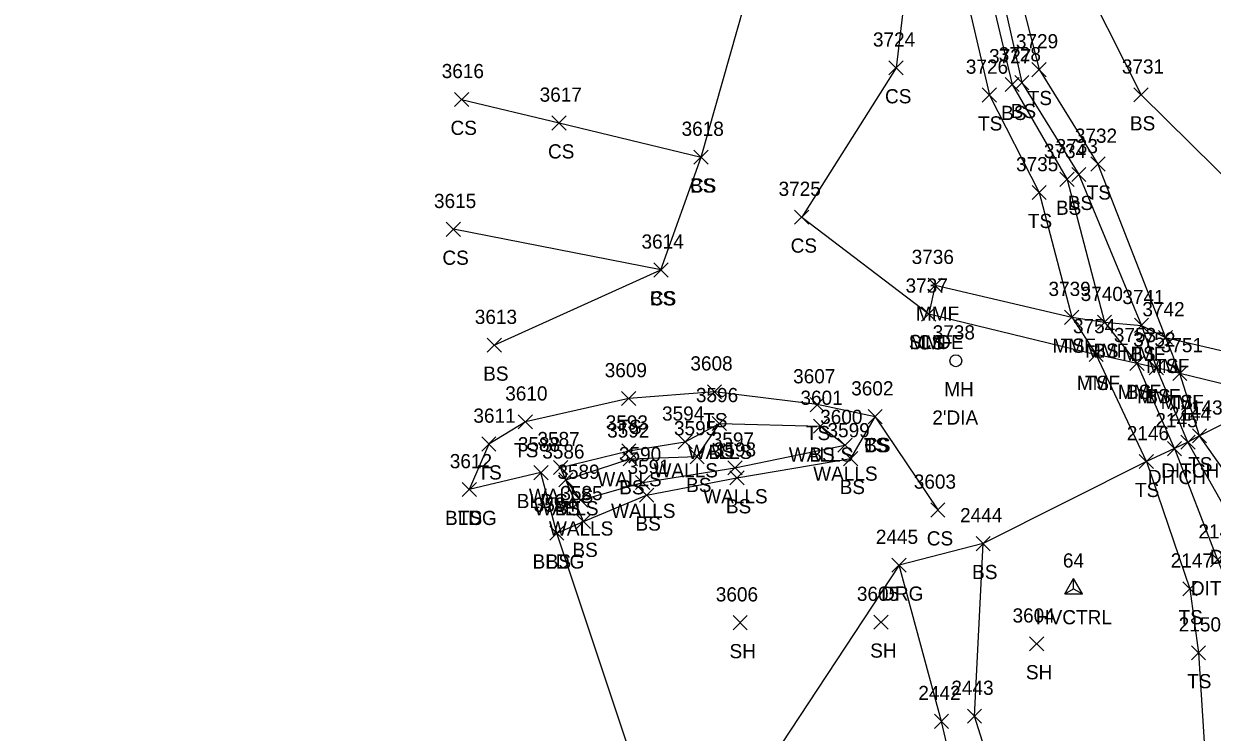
# Model space of a CAD drawing. Extents: x 49137 to 50946, y 9590 to 10709.
# Drawn here: x 49797.9 to 49965.3, y 10186.5 to 10286.3 of the extents above; entities that cross this region are included whole.
import ezdxf

# ---------------------------------------------------------------- set-up
doc = ezdxf.new("R2010")
doc.units = 0
for name, color, linetype in [('C_A', 7, 'Continuous'), ('C_I', 7, 'Continuous'), ('CPSM', 7, 'Continuous'), ('D_A', 7, 'Continuous'), ('D_I', 7, 'Continuous'), ('D_TIC', 7, 'Continuous'), ('DD', 7, 'Continuous'), ('L_A', 7, 'Continuous'), ('L_C', 7, 'Continuous'), ('L_I', 7, 'Continuous'), ('L_TIC', 7, 'Continuous'), ('LBC', 7, 'Continuous'), ('LDEFAULT', 7, 'Continuous'), ('LELB', 7, 'Continuous'), ('LSOGP', 7, 'Continuous'), ('LWS', 7, 'Continuous'), ('R_A', 7, 'Continuous'), ('R_I', 7, 'Continuous'), ('R_TIC', 7, 'Continuous'), ('RDG', 7, 'Continuous'), ('U_A', 7, 'Continuous'), ('U_C', 7, 'Continuous'), ('U_I', 7, 'Continuous'), ('UDEFAULT', 7, 'Continuous'), ('UUMH', 7, 'Continuous')]:
    doc.layers.add(name, color=color, linetype=linetype)

msp = doc.modelspace()

# ---------------------------------------------------------------- linework, layer by layer
at = {"layer": 'CPSM'}
for p, q in [((49944.49, 10206.01), (49945.74, 10208.17)), ((49946.99, 10206.01), (49945.74, 10208.17)), ((49945.74, 10206.73), (49945.74, 10208.17)), ((49944.49, 10206.01), (49945.74, 10206.73)), ((49944.49, 10206.01), (49946.99, 10206.01)), ((49945.74, 10206.73), (49945.74, 10206.73)), ((49945.74, 10206.73), (49946.99, 10206.01))]:
    msp.add_line(p, q, dxfattribs=at)
at = {"layer": 'D_TIC'}
for points in [[(49960.84, 10226.4), (49962.84, 10228.4)], [(49962.84, 10226.4), (49960.84, 10228.4)], [(49958.95, 10225.49), (49960.95, 10227.49)], [(49960.95, 10225.49), (49958.95, 10227.49)], [(49965.02, 10209.83), (49967.02, 10211.83)], [(49967.02, 10209.83), (49965.02, 10211.83)]]:
    msp.add_lwpolyline(points, dxfattribs=at)
at = {"layer": 'DD'}
for points in [[(49959.95, 10226.49), (49954.67, 10238.49)], [(49961.84, 10227.4), (49957.39, 10237.87)], [(49959.95, 10226.49), (49966.02, 10210.83), (49969.21, 10203.1), (49971.52, 10178.36), (49977.72, 10168.94)], [(49984.26, 10173.72), (49979.3, 10173.63), (49975.22, 10179.6), (49971.2, 10205.48), (49968.69, 10215.24), (49961.84, 10227.4)]]:
    msp.add_lwpolyline(points, dxfattribs=at)
at = {"layer": 'L_TIC'}
for points in [[(49919.74, 10279.13), (49921.74, 10281.13)], [(49921.74, 10279.13), (49919.74, 10281.13)], [(49939.87, 10278.88), (49941.87, 10280.88)], [(49941.87, 10278.88), (49939.87, 10280.88)], [(49936.09, 10276.78), (49938.09, 10278.78)], [(49938.09, 10276.78), (49936.09, 10278.78)], [(49937.45, 10277.05), (49939.45, 10279.05)], [(49939.45, 10277.05), (49937.45, 10279.05)], [(49858.55, 10274.68), (49860.55, 10276.68)], [(49860.55, 10274.68), (49858.55, 10276.68)], [(49932.87, 10275.3), (49934.87, 10277.3)], [(49934.87, 10275.3), (49932.87, 10277.3)], [(49954.23, 10275.32), (49956.23, 10277.32)], [(49956.23, 10275.32), (49954.23, 10277.32)], [(49872.28, 10271.36), (49874.28, 10273.36)], [(49874.28, 10271.36), (49872.28, 10273.36)], [(49892.27, 10266.55), (49894.27, 10268.55)], [(49894.27, 10266.55), (49892.27, 10268.55)], [(49892.27, 10266.55), (49894.27, 10268.55)], [(49894.27, 10266.55), (49892.27, 10268.55)], [(49948.17, 10265.57), (49950.17, 10267.57)], [(49950.17, 10265.57), (49948.17, 10267.57)], [(49943.81, 10263.42), (49945.81, 10265.42)], [(49945.81, 10263.42), (49943.81, 10265.42)], [(49945.47, 10264.1), (49947.47, 10266.1)], [(49947.47, 10264.1), (49945.47, 10266.1)], [(49939.89, 10261.56), (49941.89, 10263.56)], [(49941.89, 10261.56), (49939.89, 10263.56)], [(49906.45, 10258.09), (49908.45, 10260.09)], [(49908.45, 10258.09), (49906.45, 10260.09)], [(49857.4, 10256.38), (49859.4, 10258.38)], [(49859.4, 10256.38), (49857.4, 10258.38)], [(49886.63, 10250.66), (49888.63, 10252.66)], [(49888.63, 10250.66), (49886.63, 10252.66)], [(49886.63, 10250.66), (49888.63, 10252.66)], [(49888.63, 10250.66), (49886.63, 10252.66)], [(49925.25, 10248.5), (49927.25, 10250.5)], [(49927.25, 10248.5), (49925.25, 10250.5)], [(49925.25, 10248.5), (49927.25, 10250.5)], [(49927.25, 10248.5), (49925.25, 10250.5)], [(49924.33, 10244.46), (49926.33, 10246.46)], [(49926.33, 10244.46), (49924.33, 10246.46)], [(49924.33, 10244.46), (49926.33, 10246.46)], [(49926.33, 10244.46), (49924.33, 10246.46)], [(49944.47, 10243.99), (49946.47, 10245.99)], [(49946.47, 10243.99), (49944.47, 10245.99)], [(49944.47, 10243.99), (49946.47, 10245.99)], [(49946.47, 10243.99), (49944.47, 10245.99)], [(49949.08, 10243.28), (49951.08, 10245.28)], [(49951.08, 10243.28), (49949.08, 10245.28)], [(49949.08, 10243.28), (49951.08, 10245.28)], [(49951.08, 10243.28), (49949.08, 10245.28)], [(49954.29, 10242.85), (49956.29, 10244.85)], [(49956.29, 10242.85), (49954.29, 10244.85)], [(49954.29, 10242.85), (49956.29, 10244.85)], [(49956.29, 10242.85), (49954.29, 10244.85)], [(49957.68, 10241.13), (49959.68, 10243.13)], [(49959.68, 10241.13), (49957.68, 10243.13)], [(49957.68, 10241.13), (49959.68, 10243.13)], [(49959.68, 10241.13), (49957.68, 10243.13)], [(49863.15, 10240.05), (49865.15, 10242.05)], [(49865.15, 10240.05), (49863.15, 10242.05)], [(49947.91, 10238.74), (49949.91, 10240.74)], [(49949.91, 10238.74), (49947.91, 10240.74)], [(49947.91, 10238.74), (49949.91, 10240.74)], [(49949.91, 10238.74), (49947.91, 10240.74)], [(49947.91, 10238.74), (49949.91, 10240.74)], [(49949.91, 10238.74), (49947.91, 10240.74)], [(49953.67, 10237.49), (49955.67, 10239.49)], [(49955.67, 10237.49), (49953.67, 10239.49)], [(49953.67, 10237.49), (49955.67, 10239.49)], [(49955.67, 10237.49), (49953.67, 10239.49)], [(49956.39, 10236.87), (49958.39, 10238.87)], [(49958.39, 10236.87), (49956.39, 10238.87)], [(49956.39, 10236.87), (49958.39, 10238.87)], [(49958.39, 10236.87), (49956.39, 10238.87)], [(49959.7, 10236.06), (49961.7, 10238.06)], [(49961.7, 10236.06), (49959.7, 10238.06)], [(49959.7, 10236.06), (49961.7, 10238.06)], [(49961.7, 10236.06), (49959.7, 10238.06)], [(49882.09, 10232.54), (49884.09, 10234.54)], [(49884.09, 10232.54), (49882.09, 10234.54)], [(49894.16, 10233.49), (49896.16, 10235.49)], [(49896.16, 10233.49), (49894.16, 10235.49)], [(49908.63, 10231.68), (49910.63, 10233.68)], [(49910.63, 10231.68), (49908.63, 10233.68)], [(49867.53, 10229.26), (49869.53, 10231.26)], [(49869.53, 10229.26), (49867.53, 10231.26)], [(49894.86, 10229.03), (49896.86, 10231.03)], [(49896.86, 10229.03), (49894.86, 10231.03)], [(49894.86, 10229.03), (49896.86, 10231.03)], [(49896.86, 10229.03), (49894.86, 10231.03)], [(49916.8, 10229.98), (49918.8, 10231.98)], [(49918.8, 10229.98), (49916.8, 10231.98)], [(49916.8, 10229.98), (49918.8, 10231.98)], [(49918.8, 10229.98), (49916.8, 10231.98)], [(49916.8, 10229.98), (49918.8, 10231.98)], [(49918.8, 10229.98), (49916.8, 10231.98)], [(49909.09, 10228.65), (49911.09, 10230.65)], [(49911.09, 10228.65), (49909.09, 10230.65)], [(49909.09, 10228.65), (49911.09, 10230.65)], [(49911.09, 10228.65), (49909.09, 10230.65)], [(49862.38, 10226.13), (49864.38, 10228.13)], [(49864.38, 10226.13), (49862.38, 10228.13)], [(49890.04, 10226.43), (49892.04, 10228.43)], [(49892.04, 10226.43), (49890.04, 10228.43)], [(49912.53, 10225.96), (49914.53, 10227.96)], [(49914.53, 10225.96), (49912.53, 10227.96)], [(49962.46, 10227.28), (49964.46, 10229.28)], [(49964.46, 10227.28), (49962.46, 10229.28)], [(49882.11, 10225.17), (49884.11, 10227.17)], [(49884.11, 10225.17), (49882.11, 10227.17)], [(49882.31, 10224.04), (49884.31, 10226.04)], [(49884.31, 10224.04), (49882.31, 10226.04)], [(49891.72, 10224.36), (49893.72, 10226.36)], [(49893.72, 10224.36), (49891.72, 10226.36)], [(49913.35, 10224.08), (49915.35, 10226.08)], [(49915.35, 10224.08), (49913.35, 10226.08)], [(49872.49, 10222.83), (49874.49, 10224.83)], [(49874.49, 10222.83), (49872.49, 10224.83)], [(49897.04, 10222.77), (49899.04, 10224.77)], [(49899.04, 10222.77), (49897.04, 10224.77)], [(49954.98, 10223.66), (49956.98, 10225.66)], [(49956.98, 10223.66), (49954.98, 10225.66)], [(49869.73, 10222.1), (49871.73, 10224.1)], [(49871.73, 10222.1), (49869.73, 10224.1)], [(49873.23, 10221.08), (49875.23, 10223.08)], [(49875.23, 10221.08), (49873.23, 10223.08)], [(49873.23, 10221.08), (49875.23, 10223.08)], [(49875.23, 10221.08), (49873.23, 10223.08)], [(49873.23, 10221.08), (49875.23, 10223.08)], [(49875.23, 10221.08), (49873.23, 10223.08)], [(49884.06, 10220.71), (49886.06, 10222.71)], [(49886.06, 10220.71), (49884.06, 10222.71)], [(49897.33, 10221.36), (49899.33, 10223.36)], [(49899.33, 10221.36), (49897.33, 10223.36)], [(49859.63, 10219.72), (49861.63, 10221.72)], [(49861.63, 10219.72), (49859.63, 10221.72)], [(49859.63, 10219.72), (49861.63, 10221.72)], [(49861.63, 10219.72), (49859.63, 10221.72)], [(49884.6, 10218.93), (49886.6, 10220.93)], [(49886.6, 10218.93), (49884.6, 10220.93)], [(49875.31, 10218.23), (49877.31, 10220.23)], [(49877.31, 10218.23), (49875.31, 10220.23)], [(49925.61, 10216.84), (49927.61, 10218.84)], [(49927.61, 10216.84), (49925.61, 10218.84)], [(49875.72, 10215.22), (49877.72, 10217.22)], [(49877.72, 10215.22), (49875.72, 10217.22)], [(49875.72, 10215.22), (49877.72, 10217.22)], [(49877.72, 10215.22), (49875.72, 10217.22)], [(49871.96, 10213.58), (49873.96, 10215.58)], [(49873.96, 10213.58), (49871.96, 10215.58)], [(49871.96, 10213.58), (49873.96, 10215.58)], [(49873.96, 10213.58), (49871.96, 10215.58)], [(49932.01, 10212.1), (49934.01, 10214.1)], [(49934.01, 10212.1), (49932.01, 10214.1)], [(49961.11, 10205.73), (49963.11, 10207.73)], [(49963.11, 10205.73), (49961.11, 10207.73)], [(49897.79, 10200.95), (49899.79, 10202.95)], [(49899.79, 10200.95), (49897.79, 10202.95)], [(49917.61, 10201.03), (49919.61, 10203.03)], [(49919.61, 10201.03), (49917.61, 10203.03)], [(49939.53, 10197.98), (49941.53, 10199.98)], [(49941.53, 10197.98), (49939.53, 10199.98)], [(49962.32, 10196.72), (49964.32, 10198.72)], [(49964.32, 10196.72), (49962.32, 10198.72)], [(49930.78, 10187.79), (49932.78, 10189.79)], [(49932.78, 10187.79), (49930.78, 10189.79)]]:
    msp.add_lwpolyline(points, dxfattribs=at)
at = {"layer": 'LBC'}
msp.add_lwpolyline([(49886.35, 10174.43), (49872.96, 10214.58), (49870.73, 10223.1), (49860.63, 10220.72)], dxfattribs=at)
at = {"layer": 'LDEFAULT'}
for points in [[(49926.25, 10249.5), (49925.33, 10245.46), (49948.91, 10239.74)], [(49926.25, 10249.5), (49945.47, 10244.99), (49950.08, 10244.28), (49955.29, 10243.85), (49958.68, 10242.13), (49976.79, 10237.9), (49981.12, 10236.31), (49980.64, 10236.74), (49984.58, 10236.53), (49987.33, 10233.02), (49980.77, 10231.3), (49980.38, 10232.29), (49960.7, 10237.06), (49957.39, 10237.87), (49954.67, 10238.49), (49948.91, 10239.74)]]:
    msp.add_lwpolyline(points, dxfattribs=at)
at = {"layer": 'LELB'}
for points in [[(49903.91, 10403.07), (49911.31, 10397.95), (49908.98, 10377.05), (49918.92, 10344.46), (49924.88, 10314.97), (49933.87, 10276.3), (49940.89, 10262.56), (49945.47, 10244.99), (49948.91, 10239.74)], [(49919, 10397.71), (49918.47, 10395.67), (49914.7, 10377.7), (49922.18, 10345.09), (49927.91, 10316.2), (49937.09, 10277.78), (49944.81, 10264.42), (49950.08, 10244.28), (49954.67, 10238.49)], [(49920.18, 10395.53), (49916.78, 10377.62), (49924.17, 10345.46), (49929.67, 10317.09), (49938.45, 10278.05), (49946.47, 10265.1), (49955.29, 10243.85), (49957.39, 10237.87)], [(49921.91, 10391.69), (49918.73, 10377.87), (49926.54, 10346.6), (49931.19, 10317.78), (49940.87, 10279.88), (49949.17, 10266.57), (49958.68, 10242.13), (49960.7, 10237.06)], [(49968.85, 10355.12), (49955.47, 10336.04), (49948.52, 10322.54), (49945.71, 10295.25), (49955.23, 10276.32), (49969.26, 10262.53), (49976.79, 10237.9)], [(49864.15, 10241.05), (49887.63, 10251.66), (49893.27, 10267.55), (49900.39, 10292.56), (49898.89, 10317.9), (49893.4, 10350.47)], [(49924.88, 10314.97), (49920.74, 10280.13), (49907.45, 10259.09), (49925.33, 10245.46)], [(49859.55, 10275.68), (49873.28, 10272.36), (49893.27, 10267.55)], [(49887.63, 10251.66), (49858.4, 10257.38)], [(49955.98, 10224.66), (49948.91, 10239.74)], [(49963.46, 10228.28), (49960.7, 10237.06)], [(49917.8, 10230.98), (49909.63, 10232.68), (49895.16, 10234.49), (49883.09, 10233.54), (49868.53, 10230.26), (49863.38, 10227.13), (49860.63, 10220.72)], [(49872.96, 10214.58), (49876.72, 10216.22), (49885.6, 10219.93), (49898.33, 10222.36), (49914.35, 10225.08), (49917.8, 10230.98)], [(49917.8, 10230.98), (49926.61, 10217.84)], [(49876.72, 10216.22), (49874.23, 10222.08), (49883.31, 10225.04), (49892.72, 10225.36), (49895.86, 10230.03), (49910.09, 10229.65)], [(50070.14, 10189.73), (50073.04, 10198.84), (50071.51, 10210.93), (50064.89, 10215.85), (50042.77, 10220.38), (50023.69, 10220.9), (49995.07, 10218.25), (49980.25, 10215.79), (49975.39, 10206.16), (49978.31, 10180.83), (49976.37, 10180.49), (49973.22, 10205.26), (49972.52, 10215.46), (49963.46, 10228.28)], [(49955.98, 10224.66), (49962.11, 10206.73), (49963.32, 10197.72), (49964.68, 10176.23), (49967.05, 10162.1), (49944.13, 10145.25), (49928.38, 10128.24), (49921.48, 10115.09), (49920.1, 10100.3), (49918.19, 10083.85), (49918.93, 10078.25)], [(49897.76, 10120.11), (49909.39, 10127.66), (49927.87, 10136.88), (49941.26, 10158.78), (49931.78, 10188.79), (49933.01, 10213.1)]]:
    msp.add_lwpolyline(points, dxfattribs=at)
at = {"layer": 'LSOGP'}
msp.add_lwpolyline([(50112.88, 10184.8), (50111, 10191.05), (50108.59, 10193.82), (50108.42, 10194.29), (50115.92, 10212.32), (50113.93, 10224.33), (50084.34, 10234.53), (50067.52, 10241.32), (50048.86, 10244.33), (50032.18, 10245.84), (50010.52, 10246.66), (49989.39, 10241.14), (49963.46, 10228.29), (49961.84, 10227.4), (49959.95, 10226.5), (49955.98, 10224.67), (49933.01, 10213.1), (49921.15, 10210.06), (49900.78, 10179.13)], dxfattribs=at)
at = {"layer": 'LWS'}
for points in [[(49874.23, 10222.08), (49873.49, 10223.83), (49883.11, 10226.17), (49891.04, 10227.43), (49895.86, 10230.03)], [(49874.23, 10222.08), (49876.31, 10219.23), (49885.06, 10221.71), (49898.04, 10223.77), (49913.53, 10226.96), (49910.09, 10229.65)]]:
    msp.add_lwpolyline(points, dxfattribs=at)
at = {"layer": 'R_TIC'}
for points in [[(49920.15, 10209.06), (49922.15, 10211.06)], [(49922.15, 10209.06), (49920.15, 10211.06)], [(49926.13, 10187.06), (49928.13, 10189.06)], [(49928.13, 10187.06), (49926.13, 10189.06)]]:
    msp.add_lwpolyline(points, dxfattribs=at)
at = {"layer": 'RDG'}
msp.add_lwpolyline([(49797.89, 10003.45), (49806.67, 10020.9), (49821.46, 10037.44), (49832.34, 10049.67), (49852.34, 10071.47), (49882.42, 10103.69), (49897.76, 10120.11), (49908.6, 10130.27), (49922.11, 10142.03), (49933.26, 10161.9), (49927.13, 10188.06), (49921.15, 10210.06)], dxfattribs=at)
at = {"layer": 'UDEFAULT'}
for points in [[(49930.78, 10187.79), (49932.78, 10189.79)], [(49932.78, 10187.79), (49930.78, 10189.79)]]:
    msp.add_lwpolyline(points, dxfattribs=at)
at = {"layer": 'UUMH'}
for p, q in [((49929.15, 10238.86), (49929.15, 10238.86)), ((49929.99, 10238.86), (49929.99, 10238.86))]:
    msp.add_line(p, q, dxfattribs=at)
msp.add_circle((49929.15, 10238.86), 0.833, dxfattribs=at)

# ---------------------------------------------------------------- texts
at = {"layer": 'C_A'}
msp.add_text('HVCTRL', height=2, dxfattribs=at).set_placement((49940.43, 10201.73))
at = {"layer": 'C_I'}
msp.add_text('64', height=2, dxfattribs=at).set_placement((49944.23, 10209.73))
at = {"layer": 'D_A'}
for p in [(49958.08, 10222.4), (49956.19, 10221.49), (49964.93, 10210.24), (49962.25, 10205.83)]:
    msp.add_text('DITCH', height=2, dxfattribs=at).set_placement(p)
at = {"layer": 'D_I'}
for s, p in [('2145', (49957.26, 10229.49)), ('2144', (49959.15, 10230.4)), ('2148', (49963.32, 10213.83))]:
    msp.add_text(s, height=2, dxfattribs=at).set_placement(p)
at = {"layer": 'L_A'}
for s, p in [('CS', (49919.18, 10275.13)), ('TS', (49939.28, 10274.88)), ('BS', (49935.53, 10272.78)), ('BS', (49936.89, 10273.05)), ('TS', (49932.28, 10271.3)), ('BS', (49953.67, 10271.32)), ('CS', (49857.99, 10270.68)), ('CS', (49871.72, 10267.36)), ('CS', (49891.71, 10262.55)), ('BS', (49891.71, 10262.55)), ('TS', (49947.58, 10261.57)), ('BS', (49943.25, 10259.42)), ('BS', (49944.91, 10260.1)), ('TS', (49939.3, 10257.56)), ('CS', (49905.89, 10254.09)), ('CS', (49856.85, 10252.38)), ('CS', (49886.07, 10246.66)), ('BS', (49886.07, 10246.66)), ('MMF', (49923.53, 10244.5)), ('MMF', (49923.53, 10244.5)), ('MMF', (49922.62, 10240.46)), ('CS', (49923.77, 10240.46)), ('MMF', (49942.75, 10239.99)), ('TS', (49943.88, 10239.99)), ('MMF', (49947.36, 10239.28)), ('BS', (49948.52, 10239.28)), ('MMF', (49952.57, 10238.85)), ('BS', (49953.73, 10238.85)), ('BS', (49862.59, 10236.05)), ('MMF', (49955.96, 10237.13)), ('TS', (49957.09, 10237.13)), ('MMF', (49946.19, 10234.74)), ('MMF', (49946.19, 10234.74)), ('TS', (49947.31, 10234.74)), ('MMF', (49951.96, 10233.49)), ('BS', (49953.11, 10233.49)), ('MMF', (49954.67, 10232.87)), ('BS', (49955.83, 10232.87)), ('MMF', (49957.99, 10232.06)), ('TS', (49959.11, 10232.06)), ('TS', (49893.57, 10229.49)), ('TS', (49881.5, 10228.54)), ('TS', (49908.04, 10227.68)), ('TS', (49916.21, 10225.98)), ('CS', (49916.24, 10225.98)), ('BS', (49916.24, 10225.98)), ('TS', (49866.94, 10225.26)), ('WALLS', (49891.4, 10225.03)), ('BS', (49894.3, 10225.03)), ('WALLS', (49905.63, 10224.65)), ('BS', (49908.53, 10224.65)), ('WALLS', (49886.58, 10222.43)), ('TS', (49961.87, 10223.28)), ('TS', (49861.79, 10222.13)), ('WALLS', (49878.66, 10221.17)), ('WALLS', (49909.07, 10221.96)), ('BS', (49881.75, 10220.04)), ('BS', (49891.17, 10220.36)), ('BS', (49912.79, 10220.08)), ('TS', (49954.39, 10219.66)), ('BLDG', (49867.32, 10218.1)), ('WALLS', (49869.03, 10218.83)), ('WALLS', (49893.58, 10218.77)), ('BS', (49896.77, 10217.36)), ('BLDG', (49857.22, 10215.72)), ('TS', (49859.04, 10215.72)), ('WALLS', (49869.77, 10217.08)), ('WALLS', (49869.77, 10217.08)), ('BS', (49872.67, 10217.08)), ('WALLS', (49880.6, 10216.71)), ('WALLS', (49871.85, 10214.23)), ('BS', (49884.04, 10214.93)), ('CS', (49925.06, 10212.84)), ('BS', (49875.16, 10211.22)), ('BS', (49875.16, 10211.22)), ('BLDG', (49869.55, 10209.58)), ('BS', (49871.4, 10209.58)), ('BS', (49931.45, 10208.1)), ('TS', (49960.52, 10201.73)), ('SH', (49897.28, 10196.95)), ('SH', (49917.09, 10197.03)), ('SH', (49939.02, 10193.98)), ('TS', (49961.73, 10192.72))]:
    msp.add_text(s, height=2, dxfattribs=at).set_placement(p)
at = {"layer": 'L_C'}
msp.add_text('SLIDE', height=2, dxfattribs=at).set_placement((49922.52, 10240.5))
msp.add_text('SLIDE', height=2, dxfattribs=at).set_placement((49922.52, 10240.5))
at = {"layer": 'L_I'}
for s, p in [('3724', (49917.48, 10283.13)), ('3729', (49937.61, 10282.88)), ('3728', (49935.19, 10281.05)), ('3726', (49930.56, 10279.3)), ('3727', (49933.83, 10280.78)), ('3731', (49952.53, 10279.32)), ('3616', (49856.75, 10278.68)), ('3617', (49870.54, 10275.36)), ('3618', (49890.53, 10270.55)), ('3618', (49890.53, 10270.55)), ('3732', (49945.91, 10269.57)), ('3733', (49943.21, 10268.1)), ('3734', (49941.55, 10267.42)), ('3735', (49937.63, 10265.56)), ('3725', (49904.19, 10262.09)), ('3615', (49855.66, 10260.38)), ('3614', (49884.89, 10254.66)), ('3614', (49884.89, 10254.66)), ('3736', (49922.93, 10252.5)), ('3736', (49922.93, 10252.5)), ('3737', (49922.07, 10248.46)), ('3737', (49922.07, 10248.46)), ('3739', (49942.2, 10247.99)), ('3739', (49942.2, 10247.99)), ('3740', (49946.73, 10247.28)), ('3740', (49946.73, 10247.28)), ('3741', (49952.6, 10246.85)), ('3741', (49952.6, 10246.85)), ('3613', (49861.41, 10244.05)), ('3742', (49955.42, 10245.13)), ('3742', (49955.42, 10245.13)), ('3754', (49945.65, 10242.74)), ('3754', (49945.65, 10242.74)), ('3754', (49945.65, 10242.74)), ('3753', (49951.41, 10241.49)), ('3753', (49951.41, 10241.49)), ('3752', (49954.13, 10240.87)), ('3752', (49954.13, 10240.87)), ('3751', (49958.01, 10240.06)), ('3751', (49958.01, 10240.06)), ('3608', (49891.77, 10237.49)), ('3609', (49879.7, 10236.54)), ('3607', (49906.24, 10235.68)), ('3602', (49914.42, 10233.98)), ('3602', (49914.42, 10233.98)), ('3602', (49914.42, 10233.98)), ('3610', (49865.7, 10233.26)), ('3596', (49892.55, 10233.03)), ('3596', (49892.55, 10233.03)), ('3601', (49907.27, 10232.65)), ('3601', (49907.27, 10232.65)), ('2143', (49960.77, 10231.28)), ('3611', (49861.21, 10230.13)), ('3593', (49879.85, 10229.17)), ('3594', (49887.78, 10230.43)), ('3600', (49910.05, 10229.96)), ('3592', (49880.05, 10228.04)), ('3595', (49889.46, 10228.36)), ('3599', (49911.08, 10228.08)), ('2146', (49953.23, 10227.66)), ('3588', (49867.47, 10226.1)), ('3587', (49870.23, 10226.83)), ('3597', (49894.78, 10226.77)), ('3586', (49870.91, 10225.08)), ('3586', (49870.91, 10225.08)), ('3586', (49870.91, 10225.08)), ('3590', (49881.71, 10224.71)), ('3598', (49895.07, 10225.36)), ('3612', (49857.89, 10223.72)), ('3612', (49857.89, 10223.72)), ('3591', (49882.91, 10222.93)), ('3589', (49873.04, 10222.23)), ('3603', (49923.23, 10220.84)), ('3585', (49873.46, 10219.22)), ('3585', (49873.46, 10219.22)), ('3584', (49869.7, 10217.58)), ('3584', (49869.7, 10217.58)), ('2444', (49929.75, 10216.1)), ('2147', (49959.42, 10209.73)), ('3606', (49895.35, 10204.95)), ('3605', (49915.22, 10205.03)), ('3604', (49937.14, 10201.98)), ('2150', (49960.54, 10200.72)), ('2443', (49928.52, 10191.79))]:
    msp.add_text(s, height=2, dxfattribs=at).set_placement(p)
at = {"layer": 'R_A'}
msp.add_text('DRG', height=2, dxfattribs=at).set_placement((49918.64, 10205.06))
at = {"layer": 'R_I'}
for s, p in [('2445', (49917.89, 10213.06)), ('2442', (49923.87, 10191.06))]:
    msp.add_text(s, height=2, dxfattribs=at).set_placement(p)
at = {"layer": 'U_A'}
msp.add_text('MH', height=2, dxfattribs=at).set_placement((49927.52, 10233.86))
at = {"layer": 'U_C'}
msp.add_text("2'DIA", height=2, dxfattribs=at).set_placement((49925.84, 10229.86))
at = {"layer": 'U_I'}
for s, p in [('3738', (49925.89, 10241.86)), ('2443', (49928.52, 10191.79))]:
    msp.add_text(s, height=2, dxfattribs=at).set_placement(p)

doc.saveas('drawing.dxf')
